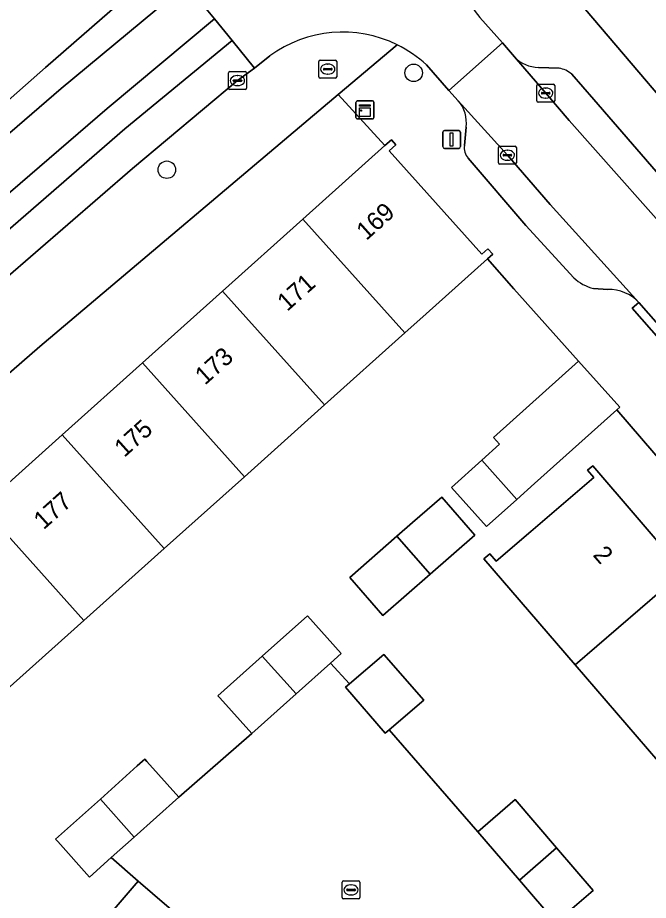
# Model space of a CAD drawing. Extents: x 162523 to 163266, y 381230 to 382050.
# Drawn here: x 162580.08 to 162615.3, y 381818.68 to 381867.97 of the extents above; entities that cross this region are included whole.
import ezdxf

# ---------------------------------------------------------------- set-up
doc = ezdxf.new("R2010")
doc.units = 0
for name, color, linetype in [('IMGEO_Boom', 7, 'Continuous'), ('IMGEO_Brandkraan', 7, 'Continuous'), ('IMGEO_Erf', 7, 'Continuous'), ('IMGEO_Fietspad_gesloten', 7, 'Continuous'), ('IMGEO_Groenvoorziening', 7, 'Continuous'), ('IMGEO_Haag', 7, 'Continuous'), ('IMGEO_Kast', 7, 'Continuous'), ('IMGEO_Kolk', 7, 'Continuous'), ('IMGEO_Lichtmast', 7, 'Continuous'), ('IMGEO_Muur', 7, 'Continuous'), ('IMGEO_Pand', 7, 'Continuous'), ('IMGEO_Pand_nummerreeks', 7, 'Continuous'), ('IMGEO_Parkeervlak_open', 7, 'Continuous'), ('IMGEO_Rijbaan_lokaal_open', 7, 'Continuous'), ('IMGEO_Rijbaan_regionaal_gesloten', 7, 'Continuous'), ('IMGEO_Voetpad_open', 7, 'Continuous')]:
    doc.layers.add(name, color=color, linetype=linetype)

msp = doc.modelspace()

# ---------------------------------------------------------------- linework, layer by layer
at = {"layer": 'IMGEO_Boom'}
for centre in [(162602.194, 381864.883), (162588.407, 381859.474)]:
    msp.add_circle(centre, 0.489, dxfattribs=at)
at = {"layer": 'IMGEO_Brandkraan'}
for p, q in [((162596.894, 381864.666), (162596.894, 381865.518)), ((162596.969, 381865.592), (162597.821, 381865.592)), ((162597.895, 381865.518), (162597.895, 381864.666)), ((162597.153, 381865.086), (162597.153, 381865.098)), ((162597.591, 381865.049), (162597.193, 381865.049)), ((162597.196, 381865.135), (162597.594, 381865.135)), ((162597.382, 381865.372), (162597.407, 381865.372)), ((162597.637, 381865.098), (162597.637, 381865.086)), ((162597.821, 381864.592), (162596.969, 381864.592)), ((162597.405, 381864.812), (162597.38, 381864.812))]:
    msp.add_line(p, q, dxfattribs=at)
for points in [[(162596.894, 381864.666), (162596.894, 381865.518)], [(162596.969, 381865.592), (162597.821, 381865.592)], [(162597.895, 381865.518), (162597.895, 381864.666)], [(162597.821, 381864.592), (162596.969, 381864.592)]]:
    msp.add_lwpolyline(points, dxfattribs=at)
for centre, radius, start, end in [((162596.971, 381865.516), 0.0765, 91.552, 178.448), ((162596.971, 381865.516), 0.0765, 91.552, 178.448), ((162597.819, 381865.516), 0.0765, 1.552, 88.448), ((162597.819, 381865.516), 0.0765, 1.552, 88.448), ((162597.193, 381865.095), 0.0403, 85.8775, 175.7526), ((162597.19, 381865.085), 0.0366, 178.938, 274.7102), ((162597.594, 381865.092), 0.043, 264.8664, 352.4533), ((162597.598, 381865.097), 0.0386, 1.7309, 96.639), ((162596.971, 381864.668), 0.0765, 181.552, 268.448), ((162596.971, 381864.668), 0.0765, 181.552, 268.448), ((162597.819, 381864.668), 0.0765, 271.552, 358.448), ((162597.819, 381864.668), 0.0765, 271.552, 358.448)]:
    msp.add_arc(centre, radius, start, end, dxfattribs=at)
for centre, major_axis, ratio, start_param, end_param in [((162597.381, 381865.092), (-0.387, 0.002), 0.722429, 4.712389, 7.853982), ((162597.406, 381865.092), (-0.39, 0.002), 0.717154, 1.570796, 4.712389)]:
    msp.add_ellipse(centre, major_axis=major_axis, ratio=ratio, start_param=start_param, end_param=end_param, dxfattribs=at)
at = {"layer": 'IMGEO_Erf'}
for points in [[(162625.011, 381886.086), (162608.447, 381872.351), (162617.656, 381861.527)], [(162578.085, 381840.657), (162582.563, 381844.671), (162587.041, 381848.684), (162591.518, 381852.697), (162596.004, 381856.717), (162600.585, 381860.822), (162597.983, 381863.68), (162581.307, 381849.596), (162563.057, 381833.73)], [(162637.769, 381817.908), (162613.536, 381846.073), (162608.946, 381841.96), (162607.949, 381841.067), (162606.255, 381839.549), (162604.298, 381841.733), (162605.992, 381843.251), (162606.989, 381844.144), (162606.643, 381844.53), (162611.397, 381848.79), (162607.795, 381852.831), (162606.311, 381854.495), (162602.884, 381851.424), (162601.7, 381850.363), (162597.214, 381846.343), (162592.736, 381842.329), (162588.257, 381838.316), (162583.779, 381834.303), (162579.309, 381830.297)], [(162615.822, 381826.466), (162611.203, 381831.833), (162606.117, 381837.742), (162606.445, 381838.024), (162606.802, 381837.609), (162608.744, 381839.28), (162612.249, 381842.296), (162611.907, 381842.694), (162612.192, 381842.939), (162617.262, 381837.048), (162621.883, 381831.678), (162626.444, 381826.379), (162630.902, 381821.198), (162635.455, 381815.908)], [(162583.554, 381815.958), (162586.812, 381819.75), (162585.305, 381821.062), (162584.09, 381819.973), (162582.313, 381821.956), (162582.194, 381822.089), (162584.7, 381824.334), (162586.76, 381826.18), (162587.055, 381826.444), (162587.178, 381826.554), (162587.297, 381826.422), (162589.074, 381824.44), (162593.148, 381827.986), (162591.362, 381829.978), (162591.26, 381830.091), (162593.737, 381832.31), (162596.262, 381834.573), (162598.149, 381832.467), (162597.546, 381831.927), (162598.608, 381830.759), (162600.53, 381832.413), (162602.755, 381829.864), (162600.819, 381828.198), (162605.774, 381822.512), (162607.852, 381824.301), (162610.175, 381821.601), (162612.212, 381819.235), (162610.133, 381817.446)]]:
    msp.add_lwpolyline(points, dxfattribs=at)
msp.add_lwpolyline([(162600.477, 381834.583), (162598.622, 381836.706), (162601.253, 381839.005), (162602.131, 381839.773), (162603.759, 381841.195), (162605.614, 381839.072), (162603.12, 381836.893)], close=True, dxfattribs=at)
at = {"layer": 'IMGEO_Fietspad_gesloten'}
for points in [[(162586.056, 381861.754), (162592.049, 381866.695), (162591.078, 381867.896), (162585.082, 381862.888), (162568.19, 381848.358)], [(162557.574, 381836.413), (162558.305, 381837.166), (162558.429, 381837.287), (162561.681, 381840.461), (162566.047, 381844.39), (162586.056, 381861.754)]]:
    msp.add_lwpolyline(points, dxfattribs=at)
at = {"layer": 'IMGEO_Groenvoorziening'}
for points in [[(162680.739, 381946.928), (162671.529, 381939.448), (162665.643, 381934.608), (162662.907, 381932.358), (162646.842, 381919.202), (162628.275, 381903.978), (162616.901, 381894.769), (162600.282, 381881.209), (162593.659, 381875.675), (162587.814, 381870.584), (162581.631, 381865.192), (162576.654, 381860.802), (162570.541, 381855.349), (162568.79, 381853.73), (162563.048, 381848.267), (162562.147, 381847.417)], [(162562.824, 381846.988), (162573.602, 381856.338), (162582.504, 381864.006), (162588.508, 381868.991), (162589.487, 381869.827), (162603.985, 381881.713), (162607.58, 381884.559), (162623.559, 381897.652), (162657.024, 381924.879)]]:
    msp.add_lwpolyline(points, dxfattribs=at)
at = {"layer": 'IMGEO_Haag'}
for points in [[(162562.824, 381846.988), (162573.602, 381856.338), (162582.504, 381864.006), (162588.508, 381868.991), (162589.487, 381869.827), (162603.985, 381881.713), (162607.58, 381884.559), (162623.559, 381897.652), (162657.024, 381924.879), (162674.516, 381939.191), (162688.899, 381951.026), (162689.109, 381951.165), (162692.795, 381954.244), (162706.361, 381965.315), (162723.06, 381979.017), (162732.21, 381986.499)], [(162680.739, 381946.928), (162671.529, 381939.448), (162665.643, 381934.608), (162662.907, 381932.358), (162646.842, 381919.202), (162628.275, 381903.978), (162616.901, 381894.769), (162600.282, 381881.209), (162593.659, 381875.675), (162587.814, 381870.584), (162581.631, 381865.192), (162576.654, 381860.802), (162570.541, 381855.349), (162568.79, 381853.73), (162563.048, 381848.267), (162562.147, 381847.417)]]:
    msp.add_lwpolyline(points, dxfattribs=at)
at = {"layer": 'IMGEO_Kast'}
for p, q in [((162598.968, 381862.39), (162598.968, 381863.231)), ((162598.968, 381863.231), (162598.968, 381862.39)), ((162599.043, 381863.315), (162599.884, 381863.315)), ((162599.884, 381863.315), (162599.043, 381863.315)), ((162599.968, 381863.24), (162599.968, 381862.399)), ((162599.968, 381862.399), (162599.968, 381863.24)), ((162599.893, 381862.315), (162599.052, 381862.315)), ((162599.052, 381862.315), (162599.893, 381862.315))]:
    msp.add_line(p, q, dxfattribs=at)
for points in [[(162599.163, 381863.105), (162599.763, 381863.105), (162599.763, 381863.02), (162599.163, 381863.02), (162599.163, 381863.105)], [(162599.163, 381862.93), (162599.763, 381862.93), (162599.763, 381862.441), (162599.163, 381862.441), (162599.163, 381862.93)]]:
    msp.add_lwpolyline(points, dxfattribs=at)
msp.add_circle((162599.247, 381862.779), 0.0377, dxfattribs=at)
for centre, start, end in [((162599.046, 381863.237), 92.4484, 184.2845), ((162599.046, 381863.237), 92.4484, 184.2845), ((162599.89, 381863.237), 2.4484, 94.2845), ((162599.89, 381863.237), 2.4484, 94.2845), ((162599.046, 381862.393), 182.4484, 274.2845), ((162599.046, 381862.393), 182.4484, 274.2845), ((162599.89, 381862.393), 272.4484, 4.2845), ((162599.89, 381862.393), 272.4484, 4.2845)]:
    msp.add_arc(centre, 0.0779, start, end, dxfattribs=at)
at = {"layer": 'IMGEO_Kolk'}
for p, q in [((162591.927, 381864.951), (162592.779, 381864.951)), ((162591.852, 381864.025), (162591.852, 381864.877)), ((162592.111, 381864.445), (162592.111, 381864.457)), ((162592.154, 381864.494), (162592.552, 381864.494)), ((162592.34, 381864.731), (162592.365, 381864.731)), ((162592.595, 381864.457), (162592.595, 381864.445)), ((162592.853, 381864.877), (162592.853, 381864.025)), ((162592.779, 381863.951), (162591.927, 381863.951)), ((162592.549, 381864.408), (162592.151, 381864.408)), ((162592.363, 381864.171), (162592.338, 381864.171)), ((162609.066, 381863.326), (162609.066, 381864.178)), ((162609.141, 381864.252), (162609.993, 381864.252)), ((162609.554, 381864.032), (162609.579, 381864.032)), ((162610.067, 381864.178), (162610.067, 381863.326)), ((162609.325, 381863.746), (162609.325, 381863.758)), ((162609.763, 381863.709), (162609.365, 381863.709)), ((162609.368, 381863.795), (162609.766, 381863.795)), ((162609.577, 381863.472), (162609.552, 381863.472)), ((162609.809, 381863.758), (162609.809, 381863.746)), ((162609.993, 381863.252), (162609.141, 381863.252)), ((162606.925, 381859.859), (162606.925, 381860.711)), ((162607, 381860.785), (162607.852, 381860.785)), ((162607.413, 381860.565), (162607.438, 381860.565)), ((162607.926, 381860.711), (162607.926, 381859.859)), ((162607.184, 381860.279), (162607.184, 381860.291)), ((162607.622, 381860.242), (162607.224, 381860.242)), ((162607.227, 381860.328), (162607.625, 381860.328)), ((162607.436, 381860.005), (162607.411, 381860.005)), ((162607.668, 381860.291), (162607.668, 381860.279)), ((162607.852, 381859.785), (162607, 381859.785)), ((162598.193, 381818.834), (162598.193, 381819.686)), ((162598.268, 381819.76), (162599.12, 381819.76)), ((162599.194, 381819.686), (162599.194, 381818.834)), ((162598.452, 381819.254), (162598.452, 381819.266)), ((162598.89, 381819.217), (162598.492, 381819.217)), ((162598.495, 381819.303), (162598.893, 381819.303)), ((162598.681, 381819.54), (162598.706, 381819.54)), ((162598.936, 381819.266), (162598.936, 381819.254)), ((162599.12, 381818.76), (162598.268, 381818.76)), ((162598.704, 381818.98), (162598.679, 381818.98))]:
    msp.add_line(p, q, dxfattribs=at)
for points in [[(162591.927, 381864.951), (162592.779, 381864.951)], [(162591.852, 381864.025), (162591.852, 381864.877)], [(162592.853, 381864.877), (162592.853, 381864.025)], [(162592.779, 381863.951), (162591.927, 381863.951)], [(162609.066, 381863.326), (162609.066, 381864.178)], [(162609.141, 381864.252), (162609.993, 381864.252)], [(162610.067, 381864.178), (162610.067, 381863.326)], [(162609.993, 381863.252), (162609.141, 381863.252)], [(162606.925, 381859.859), (162606.925, 381860.711)], [(162607, 381860.785), (162607.852, 381860.785)], [(162607.926, 381860.711), (162607.926, 381859.859)], [(162607.852, 381859.785), (162607, 381859.785)], [(162598.193, 381818.834), (162598.193, 381819.686)], [(162598.268, 381819.76), (162599.12, 381819.76)], [(162599.194, 381819.686), (162599.194, 381818.834)], [(162599.12, 381818.76), (162598.268, 381818.76)]]:
    msp.add_lwpolyline(points, dxfattribs=at)
for centre, radius, start, end in [((162591.929, 381864.875), 0.0765, 91.552, 178.448), ((162591.929, 381864.875), 0.0765, 91.552, 178.448), ((162592.777, 381864.875), 0.0765, 1.552, 88.448), ((162592.777, 381864.875), 0.0765, 1.552, 88.448), ((162592.151, 381864.454), 0.0403, 85.8775, 175.7526), ((162592.148, 381864.444), 0.0366, 178.938, 274.7102), ((162592.552, 381864.451), 0.043, 264.8664, 352.4533), ((162592.556, 381864.456), 0.0386, 1.7309, 96.639), ((162591.929, 381864.027), 0.0765, 181.552, 268.448), ((162591.929, 381864.027), 0.0765, 181.552, 268.448), ((162592.777, 381864.027), 0.0765, 271.552, 358.448), ((162592.777, 381864.027), 0.0765, 271.552, 358.448), ((162609.143, 381864.176), 0.0765, 91.552, 178.448), ((162609.143, 381864.176), 0.0765, 91.552, 178.448), ((162609.991, 381864.176), 0.0765, 1.552, 88.448), ((162609.991, 381864.176), 0.0765, 1.552, 88.448), ((162609.365, 381863.755), 0.0403, 85.8775, 175.7526), ((162609.362, 381863.745), 0.0366, 178.938, 274.7102), ((162609.766, 381863.752), 0.043, 264.8664, 352.4533), ((162609.77, 381863.757), 0.0386, 1.7309, 96.639), ((162609.143, 381863.328), 0.0765, 181.552, 268.448), ((162609.143, 381863.328), 0.0765, 181.552, 268.448), ((162609.991, 381863.328), 0.0765, 271.552, 358.448), ((162609.991, 381863.328), 0.0765, 271.552, 358.448), ((162607.002, 381860.709), 0.0765, 91.552, 178.448), ((162607.002, 381860.709), 0.0765, 91.552, 178.448), ((162607.85, 381860.709), 0.0765, 1.552, 88.448), ((162607.85, 381860.709), 0.0765, 1.552, 88.448), ((162607.224, 381860.288), 0.0403, 85.8775, 175.7526), ((162607.221, 381860.278), 0.0366, 178.938, 274.7102), ((162607.625, 381860.285), 0.043, 264.8664, 352.4533), ((162607.629, 381860.29), 0.0386, 1.7309, 96.639), ((162607.002, 381859.861), 0.0765, 181.552, 268.448), ((162607.002, 381859.861), 0.0765, 181.552, 268.448), ((162607.85, 381859.861), 0.0765, 271.552, 358.448), ((162607.85, 381859.861), 0.0765, 271.552, 358.448), ((162598.27, 381819.684), 0.0765, 91.552, 178.448), ((162598.27, 381819.684), 0.0765, 91.552, 178.448), ((162599.118, 381819.684), 0.0765, 1.552, 88.448), ((162599.118, 381819.684), 0.0765, 1.552, 88.448), ((162598.492, 381819.263), 0.0403, 85.8775, 175.7526), ((162598.489, 381819.253), 0.0366, 178.938, 274.7102), ((162598.893, 381819.26), 0.043, 264.8664, 352.4533), ((162598.897, 381819.265), 0.0386, 1.7309, 96.639), ((162598.27, 381818.836), 0.0765, 181.552, 268.448), ((162598.27, 381818.836), 0.0765, 181.552, 268.448), ((162599.118, 381818.836), 0.0765, 271.552, 358.448), ((162599.118, 381818.836), 0.0765, 271.552, 358.448)]:
    msp.add_arc(centre, radius, start, end, dxfattribs=at)
for centre, major_axis, ratio, start_param, end_param in [((162592.339, 381864.451), (-0.387, 0.002), 0.722429, 4.712389, 7.853982), ((162592.364, 381864.451), (-0.39, 0.002), 0.717154, 1.570796, 4.712389), ((162609.553, 381863.752), (-0.387, 0.002), 0.722429, 4.712389, 7.853982), ((162609.578, 381863.752), (-0.39, 0.002), 0.717154, 1.570796, 4.712389), ((162607.412, 381860.285), (-0.387, 0.002), 0.722429, 4.712389, 7.853982), ((162607.437, 381860.285), (-0.39, 0.002), 0.717154, 1.570796, 4.712389), ((162598.68, 381819.26), (-0.387, 0.002), 0.722429, 4.712389, 7.853982), ((162598.705, 381819.26), (-0.39, 0.002), 0.717154, 1.570796, 4.712389)]:
    msp.add_ellipse(centre, major_axis=major_axis, ratio=ratio, start_param=start_param, end_param=end_param, dxfattribs=at)
at = {"layer": 'IMGEO_Lichtmast'}
for p, q in [((162603.816, 381860.764), (162603.816, 381861.564)), ((162603.816, 381861.564), (162603.816, 381860.764)), ((162603.916, 381861.664), (162604.706, 381861.664)), ((162604.706, 381861.664), (162603.916, 381861.664)), ((162604.806, 381861.564), (162604.806, 381860.764)), ((162604.806, 381860.764), (162604.806, 381861.564)), ((162604.706, 381860.664), (162603.916, 381860.664)), ((162603.916, 381860.664), (162604.706, 381860.664))]:
    msp.add_line(p, q, dxfattribs=at)
msp.add_lwpolyline([(162604.236, 381861.539), (162604.386, 381861.539), (162604.386, 381860.789), (162604.236, 381860.789), (162604.236, 381861.539)], dxfattribs=at)
for centre, start, end in [((162603.916, 381861.564), 90, 180), ((162603.916, 381861.564), 90, 180), ((162604.706, 381861.564), 0, 90), ((162604.706, 381861.564), 360, 90), ((162603.916, 381860.764), 180, 270), ((162603.916, 381860.764), 180, 270), ((162604.706, 381860.764), 270, 0), ((162604.706, 381860.764), 270, 0)]:
    msp.add_arc(centre, 0.1, start, end, dxfattribs=at)
at = {"layer": 'IMGEO_Muur'}
for points in [[(162607.795, 381852.831), (162606.311, 381854.495)], [(162600.819, 381828.198), (162605.774, 381822.512)]]:
    msp.add_lwpolyline(points, dxfattribs=at)
at = {"layer": 'IMGEO_Pand'}
for points in [[(162601.7, 381850.363), (162602.884, 381851.424), (162606.311, 381854.495), (162606.607, 381854.76), (162606.34, 381855.058), (162606.001, 381854.753), (162600.816, 381860.539), (162601.189, 381860.873), (162600.945, 381861.145), (162600.585, 381860.822), (162596.004, 381856.717)], [(162601.7, 381850.363), (162596.004, 381856.717), (162591.518, 381852.697), (162597.214, 381846.343)], [(162592.736, 381842.329), (162597.214, 381846.343), (162591.518, 381852.697), (162587.041, 381848.684)], [(162592.736, 381842.329), (162587.041, 381848.684), (162582.563, 381844.671), (162588.257, 381838.316)], [(162613.536, 381846.073), (162613.7, 381846.22), (162611.397, 381848.79), (162606.643, 381844.53), (162606.989, 381844.144), (162605.992, 381843.251), (162607.949, 381841.067), (162608.946, 381841.96)], [(162583.779, 381834.303), (162588.257, 381838.316), (162582.563, 381844.671), (162578.085, 381840.657)], [(162605.992, 381843.251), (162604.298, 381841.733), (162606.255, 381839.549), (162607.949, 381841.067)], [(162611.203, 381831.833), (162617.262, 381837.048), (162612.192, 381842.939), (162611.907, 381842.694), (162612.249, 381842.296), (162608.744, 381839.28), (162606.802, 381837.609), (162606.445, 381838.024), (162606.117, 381837.742)], [(162603.759, 381841.195), (162602.131, 381839.773), (162601.253, 381839.005), (162603.12, 381836.893), (162605.614, 381839.072)], [(162579.309, 381830.297), (162583.779, 381834.303), (162578.085, 381840.657), (162573.641, 381836.675)], [(162601.253, 381839.005), (162598.622, 381836.706), (162600.477, 381834.583), (162603.12, 381836.893)], [(162621.883, 381831.678), (162617.262, 381837.048), (162611.203, 381831.833), (162615.822, 381826.466), (162615.918, 381826.544)], [(162593.737, 381832.31), (162595.624, 381830.205), (162597.546, 381831.927), (162598.149, 381832.467), (162596.262, 381834.573)], [(162600.53, 381832.413), (162598.608, 381830.759), (162598.392, 381830.573), (162600.599, 381828.009), (162600.819, 381828.198), (162602.755, 381829.864)], [(162595.624, 381830.205), (162593.737, 381832.31), (162591.26, 381830.091), (162591.362, 381829.978), (162593.148, 381827.986)], [(162587.297, 381826.422), (162587.178, 381826.554), (162587.055, 381826.444), (162586.76, 381826.18), (162584.7, 381824.334), (162586.584, 381822.209), (162589.074, 381824.44)], [(162586.584, 381822.209), (162584.7, 381824.334), (162582.194, 381822.089), (162582.313, 381821.956), (162584.09, 381819.973), (162585.305, 381821.062)], [(162608.097, 381819.812), (162610.175, 381821.601), (162607.852, 381824.301), (162605.774, 381822.512)], [(162608.097, 381819.812), (162610.133, 381817.446), (162612.212, 381819.235), (162610.175, 381821.601)], [(162589.347, 381817.572), (162586.812, 381819.75), (162583.554, 381815.958), (162582.685, 381814.947), (162585.219, 381812.769)]]:
    msp.add_lwpolyline(points, close=True, dxfattribs=at)
at = {"layer": 'IMGEO_Parkeervlak_open'}
for points in [[(162561.944, 381837.921), (162564.129, 381840.002), (162565.606, 381841.378), (162567.295, 381842.85), (162577.447, 381851.731), (162586.484, 381859.535), (162592.352, 381864.452), (162593.31, 381865.148), (162592.049, 381866.695), (162586.056, 381861.754), (162566.047, 381844.39), (162561.681, 381840.461), (162558.429, 381837.287)], [(162607.82, 381865.771), (162609.566, 381863.752), (162610.879, 381862.225), (162617.781, 381854.439), (162626.638, 381844.343), (162637.013, 381832.223)], [(162610.311, 381865.142), (162609.166, 381865.187)], [(162636.267, 381835.667), (162612.246, 381863.392), (162611.019, 381864.806)], [(162614.774, 381852.067), (162609.819, 381857.54), (162607.427, 381860.286), (162604.684, 381863.323)], [(162605.116, 381861.856), (162605.022, 381860.828)], [(162605.233, 381860.113), (162608.464, 381856.365), (162611.139, 381853.442)], [(162612.231, 381852.845), (162613.043, 381852.794)]]:
    msp.add_lwpolyline(points, dxfattribs=at)
for centre, radius, start, end in [((162609.202, 381867.114), 1.927, 224.1696, 268.9204), ((162610.129, 381863.844), 1.311, 47.22, 82.0041), ((162603.287, 381862.114), 1.848, 351.9602, 40.857), ((162605.984, 381860.723), 0.968, 173.7882, 219.0949), ((162612.852, 381855.278), 2.511, 226.9848, 255.684), ((162613.064, 381850.419), 2.375, 43.9329, 90.5034)]:
    msp.add_arc(centre, radius, start, end, dxfattribs=at)
at = {"layer": 'IMGEO_Rijbaan_lokaal_open'}
for points in [[(162605.991, 381875.483), (162607.835, 381877.056), (162606.537, 381878.623), (162605.631, 381879.753), (162603.985, 381881.713), (162589.487, 381869.827), (162591.078, 381867.896), (162592.049, 381866.695), (162593.31, 381865.148), (162594.158, 381865.831)], [(162568.19, 381848.358), (162585.082, 381862.888), (162591.078, 381867.896), (162589.487, 381869.827), (162588.508, 381868.991), (162582.504, 381864.006), (162573.602, 381856.338), (162562.824, 381846.988)], [(162602.913, 381865.326), (162604.154, 381863.897), (162607.155, 381866.568), (162605.892, 381867.967)], [(162617.781, 381854.439), (162610.879, 381862.225), (162609.566, 381863.752), (162607.82, 381865.771), (162607.155, 381866.568), (162604.154, 381863.897), (162604.684, 381863.323), (162607.427, 381860.286), (162609.819, 381857.54), (162614.774, 381852.067), (162616.934, 381849.61)], [(162610.133, 381817.446), (162608.097, 381819.812), (162605.774, 381822.512), (162600.819, 381828.198), (162600.599, 381828.009), (162598.392, 381830.573), (162598.608, 381830.759), (162597.546, 381831.927), (162595.624, 381830.205), (162593.148, 381827.986), (162589.074, 381824.44), (162586.584, 381822.209), (162585.305, 381821.062), (162586.812, 381819.75), (162589.347, 381817.572)]]:
    msp.add_lwpolyline(points, dxfattribs=at)
for centre, radius, start, end in [((162610.232, 381871.647), 5.691, 202.5276, 220.2944), ((162598.228, 381860.251), 6.907, 63.8404, 126.104), ((162598.225, 381860.245), 6.913, 47.3072, 63.8419)]:
    msp.add_arc(centre, radius, start, end, dxfattribs=at)
at = {"layer": 'IMGEO_Rijbaan_regionaal_gesloten'}
msp.add_lwpolyline([(162542.033, 381827.792), (162551.188, 381837.076), (162562.147, 381847.417), (162563.048, 381848.267), (162568.79, 381853.73), (162570.541, 381855.349), (162576.654, 381860.802), (162581.631, 381865.192), (162587.814, 381870.584), (162593.659, 381875.675), (162600.282, 381881.209), (162616.901, 381894.769), (162628.275, 381903.978), (162646.842, 381919.202), (162662.907, 381932.358), (162665.643, 381934.608), (162671.529, 381939.448), (162680.739, 381946.928)], dxfattribs=at)
at = {"layer": 'IMGEO_Voetpad_open'}
for points in [[(162646.757, 381824.316), (162646.101, 381827.394), (162642.953, 381831.956), (162641.079, 381834.52), (162617.656, 381861.527), (162608.447, 381872.351), (162604.976, 381869.467)], [(162605.892, 381867.967), (162607.155, 381866.568), (162607.82, 381865.771)], [(162601.273, 381866.45), (162597.983, 381863.68), (162600.585, 381860.822), (162600.945, 381861.145), (162601.189, 381860.873), (162600.816, 381860.539), (162606.001, 381854.753), (162606.34, 381855.058), (162606.607, 381854.76), (162606.311, 381854.495), (162607.795, 381852.831), (162611.397, 381848.79), (162613.7, 381846.22), (162613.536, 381846.073), (162637.769, 381817.908), (162641.055, 381814.077), (162691.781, 381755.909)], [(162597.983, 381863.68), (162601.273, 381866.45)], [(162594.158, 381865.831), (162593.31, 381865.148), (162592.352, 381864.452), (162586.484, 381859.535), (162577.447, 381851.731), (162567.295, 381842.85), (162565.606, 381841.378), (162564.129, 381840.002), (162561.944, 381837.921)], [(162604.684, 381863.323), (162604.154, 381863.897), (162602.913, 381865.326)], [(162609.166, 381865.187), (162610.311, 381865.142)], [(162611.019, 381864.806), (162612.246, 381863.392), (162636.267, 381835.667)], [(162544.113, 381814.899), (162548.153, 381818.57), (162563.598, 381833.161), (162563.057, 381833.73), (162581.307, 381849.596), (162597.983, 381863.68)], [(162605.022, 381860.828), (162605.116, 381861.856)], [(162611.139, 381853.442), (162608.464, 381856.365), (162605.233, 381860.113)], [(162613.043, 381852.794), (162612.231, 381852.845)], [(162617.086, 381849.434), (162616.934, 381849.61), (162616.561, 381849.279), (162614.401, 381851.736), (162614.774, 381852.067)]]:
    msp.add_lwpolyline(points, dxfattribs=at)
msp.add_lwpolyline([(162614.774, 381852.067), (162614.401, 381851.736), (162616.561, 381849.279), (162616.934, 381849.61)], close=True, dxfattribs=at)
for centre, radius, start, end in [((162610.232, 381871.647), 5.691, 202.5276, 220.2944), ((162598.228, 381860.251), 6.907, 63.8404, 126.104), ((162598.225, 381860.245), 6.913, 47.3072, 63.8419), ((162609.202, 381867.114), 1.927, 224.1696, 268.9204), ((162610.129, 381863.844), 1.311, 47.22, 82.0041), ((162603.287, 381862.114), 1.848, 351.9602, 40.857), ((162605.984, 381860.723), 0.968, 173.7882, 219.0949), ((162612.852, 381855.278), 2.511, 226.9848, 255.684), ((162613.064, 381850.419), 2.375, 43.9329, 90.5034)]:
    msp.add_arc(centre, radius, start, end, dxfattribs=at)

# ---------------------------------------------------------------- texts
at = {"layer": 'IMGEO_Pand_nummerreeks'}
for s, rotation, p in [('169', 41.8667, (162599.55, 381855.49)), ('171', 41.8667, (162595.129, 381851.528)), ('173', 41.8667, (162590.539, 381847.414)), ('175', 41.8667, (162586.033, 381843.376)), ('177', 41.8667, (162581.527, 381839.338)), ('2', 310.7158, (162612.163, 381837.945))]:
    msp.add_text(s, height=1, rotation=rotation, dxfattribs=at).set_placement(p)

doc.saveas('drawing.dxf')
